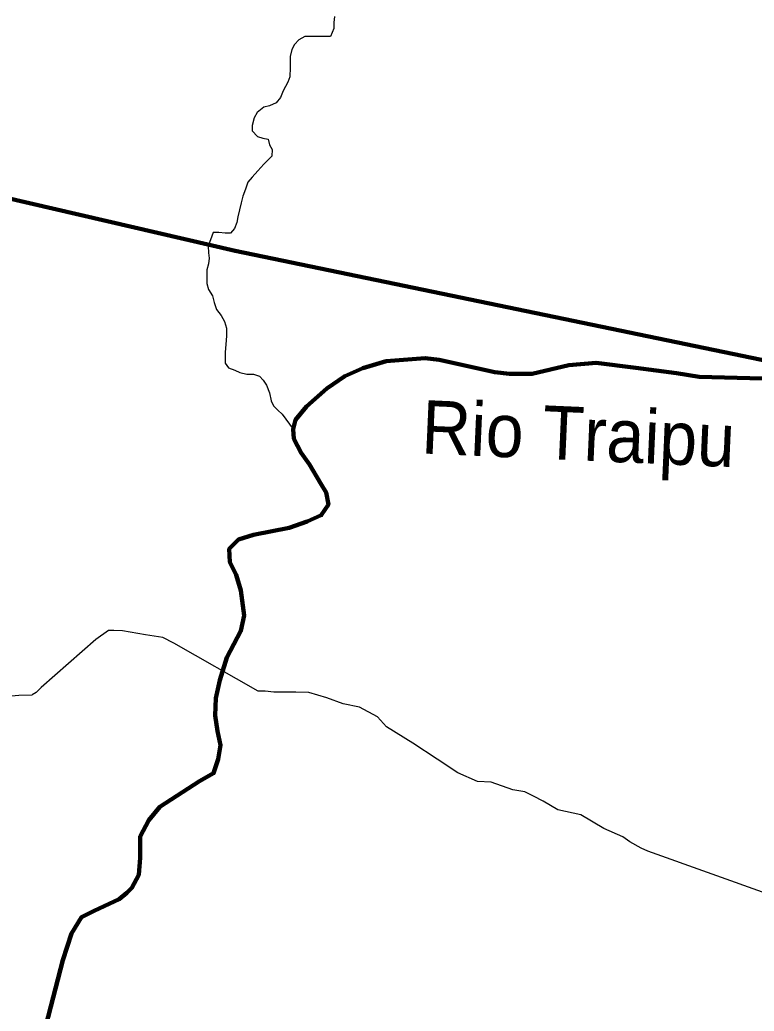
# Model space of a CAD drawing. Extents: x 553962 to 842807, y 8883888 to 9032388.
# Drawn here: x 722813 to 729677, y 8928998 to 8938264 of the extents above; entities that cross this region are included whole.
import ezdxf
from ezdxf.enums import TextEntityAlignment as Align

# ---------------------------------------------------------------- set-up
doc = ezdxf.new("R2010")
doc.units = 0
doc.header["$LTSCALE"] = 200
for name, color, linetype, lineweight in [('12', 7, 'Continuous', 25), ('24', 7, 'Continuous', 25), ('9', 7, 'Continuous', 90)]:
    doc.layers.add(name, color=color, linetype=linetype, lineweight=lineweight)
doc.layers.add('49', color=7, linetype='Continuous')

msp = doc.modelspace()

# ---------------------------------------------------------------- linework, layer by layer
at = {"layer": '12'}
for points in [[(729842.6, 8930080), (728682.6, 8930494.7), (728621.5, 8930520.3), (728514.8, 8930581.6), (728448.7, 8930627.6), (728270.7, 8930704.3), (728057.2, 8930832.1), (727843.4, 8930878.3), (727706.2, 8930960.1), (727614.7, 8931006.1), (727533.3, 8931047), (727421.3, 8931067.6), (727217.8, 8931139.3), (727090.4, 8931144.6), (726907.3, 8931226.4), (726714.2, 8931354.1), (726485.5, 8931502.3), (726241.6, 8931655.6), (726155.3, 8931747.4), (725987.5, 8931839.4), (725834.8, 8931870.3), (725682.2, 8931926.6), (725514.3, 8931977.8), (725392, 8931978.1), (725274.8, 8931978.3), (725188.2, 8931978.4), (725106.8, 8931988.8), (725040.5, 8931988.9), (724252.6, 8932438.6), (724150.9, 8932489.8), (723987.9, 8932515.5), (723774.1, 8932551.6), (723692.6, 8932556.8), (723641.7, 8932556.9), (723524.2, 8932470.5)], [(723524.2, 8932470.5), (723013.1, 8932023.2), (722964.6, 8931975.3), (722928.4, 8931953)], [(719465.7, 8931582), (719776.2, 8931594.6), (719960.1, 8931621.3), (720108, 8931671.9), (720470.6, 8931895.4), (720598.2, 8931961.4), (720664.5, 8932002), (720792.1, 8932052.7), (720970.4, 8932052.4), (721113, 8932057.2), (721235.3, 8932046.8), (721439, 8932046.4), (721540.8, 8932020.8), (721759.6, 8931949.1), (721968.3, 8931907.9), (722065, 8931877.2), (722233.1, 8931866.7), (722309.4, 8931841.1), (722477.5, 8931835.7), (722554, 8931861), (722651, 8931906.7), (722697, 8931942.3), (722804, 8931952.2), (722928.4, 8931953)]]:
    msp.add_lwpolyline(points, dxfattribs=at)
at = {"layer": '24'}
for points in [[(725753.9, 8938294.8), (725748.4, 8938238.8), (725748, 8938182.8), (725717, 8938106.6), (725544.1, 8938107.6), (725478, 8938108), (725421.8, 8938077.8), (725380.8, 8938032.2), (725355.1, 8937986.6), (725339.3, 8937920.5), (725339, 8937869.5), (725338.6, 8937818.6), (725338, 8937732.1), (725317.3, 8937681.2), (725276.1, 8937600), (725250.2, 8937539.1), (725207.8, 8937489.4), (725146.5, 8937460.6), (725092.5, 8937446.2), (725030.6, 8937397.8), (725004.8, 8937347.1), (724984, 8937275.9), (724983.6, 8937225), (725034.1, 8937173.8), (725084.8, 8937158.2), (725135.6, 8937147.7), (725145.5, 8937096.7), (725170.6, 8937050.7), (725170.1, 8936989.6), (725134.3, 8936954.2), (725093.3, 8936913.7), (725037, 8936852.9), (724985.7, 8936792.1), (724944.7, 8936746.5), (724923.9, 8936680.5), (724898, 8936614.4), (724882.3, 8936553.4), (724866.6, 8936487.3), (724850.9, 8936421.2), (724840.4, 8936370.3), (724819.6, 8936314.4), (724783.7, 8936268.8), (724732.8, 8936269.1), (724671.9, 8936274.6), (724621, 8936274.9)], [(724621, 8936274.9), (724573, 8936146.7), (724577.7, 8936085.6), (724582.4, 8936034.6), (724577, 8935983.7), (724561.3, 8935927.8), (724561, 8935876.9), (724560.4, 8935800.5), (724575.3, 8935744.4), (724615.6, 8935683), (724630.4, 8935621.8), (724650.3, 8935555.5), (724695.7, 8935499.2), (724725.8, 8935443), (724745.7, 8935381.8), (724745.2, 8935310.5), (724739.6, 8935229), (724734, 8935157.8), (724733.7, 8935106.9), (724733.3, 8935055.9), (724763.5, 8935009.9), (724824.4, 8934989.2), (724870, 8934968.5), (724936, 8934952.8), (724997.1, 8934952.5), (725052.8, 8934931.8), (725088.2, 8934895.9), (725118.4, 8934849.9), (725148.4, 8934778.4), (725163.2, 8934701.9), (725183.2, 8934656), (725223.6, 8934615), (725264, 8934579.1), (725368.5, 8934436.4)]]:
    msp.add_lwpolyline(points, dxfattribs=at)
at = {"layer": '24', "lineweight": 53}
for points in [[(726733.4, 8935086.7), (726602, 8935101.3), (726237.1, 8935072), (726018.1, 8935006.3), (725850.2, 8934933.2), (725682.3, 8934816.3), (725492.6, 8934648.3), (725390.4, 8934524.1), (725368.5, 8934436.4), (725375.8, 8934348.7), (725441.5, 8934217.2), (725521.8, 8934107.6), (725624, 8933932.2), (725675.1, 8933844.6), (725697, 8933734.9), (725631.3, 8933632.7), (725499.9, 8933574.2), (725332, 8933515.8), (724996.3, 8933450), (724857.6, 8933406.2), (724770, 8933318.5), (724777.3, 8933194.3), (724835.7, 8933077.4), (724879.5, 8932931.2), (724908.7, 8932697.4), (724879.5, 8932551.3), (724748.1, 8932302.9), (724682.4, 8932091), (724645.9, 8931922.9), (724638.6, 8931762.2), (724660.5, 8931616.1), (724689.7, 8931484.6), (724667.8, 8931353), (724624, 8931221.5), (724492.7, 8931148.4), (724120.4, 8930907.3), (724018.2, 8930783.1)], [(729755, 8934911.3), (729163.8, 8934925.9), (728952.2, 8934962.4), (728571.5, 8935009.7), (728200.4, 8935057.4), (727944.9, 8935035.5), (727601.9, 8934955.1), (727390.2, 8934955.1), (727251.6, 8934969.8), (726733.4, 8935086.7)], [(724018.2, 8930783.1), (723938, 8930629.7), (723938, 8930432.4), (723924.2, 8930271.2), (723861.2, 8930151.4), (723813.9, 8930103.6), (723741.7, 8930044.3), (723507.3, 8929935.6), (723390.6, 8929877.1), (723295.7, 8929723.7), (723215.4, 8929475.3), (723055.5, 8928859.6)]]:
    msp.add_lwpolyline(points, dxfattribs=at)
at = {"layer": '9'}
for points in [[(696242, 8937672.8), (702061.8, 8937200.5), (702208.9, 8933124.7), (710319.1, 8936704.6), (716154, 8938115.2), (724825.2, 8936103.1), (730092.7, 8935013.9)], [(726733.4, 8935086.7), (726602, 8935101.3), (726237.1, 8935072), (726018.1, 8935006.3), (725850.2, 8934933.2), (725682.3, 8934816.3), (725492.6, 8934648.3), (725390.4, 8934524.1), (725368.5, 8934436.4), (725375.8, 8934348.7), (725441.5, 8934217.2), (725521.8, 8934107.6), (725624, 8933932.2), (725675.1, 8933844.6), (725697, 8933734.9), (725631.3, 8933632.7), (725499.9, 8933574.2), (725332, 8933515.8), (724996.3, 8933450), (724857.6, 8933406.2), (724770, 8933318.5), (724777.3, 8933194.3), (724835.7, 8933077.4), (724879.5, 8932931.2), (724908.7, 8932697.4), (724879.5, 8932551.3), (724748.1, 8932302.9), (724682.4, 8932091), (724645.9, 8931922.9), (724638.6, 8931762.2), (724660.5, 8931616.1), (724689.7, 8931484.6), (724667.8, 8931353), (724624, 8931221.5), (724492.7, 8931148.4), (724120.4, 8930907.3), (724018.2, 8930783.1)], [(729755, 8934911.3), (729163.8, 8934925.9), (728952.2, 8934962.4), (728571.5, 8935009.7), (728200.4, 8935057.4), (727944.9, 8935035.5), (727601.9, 8934955.1), (727390.2, 8934955.1), (727251.6, 8934969.8), (726733.4, 8935086.7)], [(724018.2, 8930783.1), (723938, 8930629.7), (723938, 8930432.4), (723924.2, 8930271.2), (723861.2, 8930151.4), (723813.9, 8930103.6), (723741.7, 8930044.3), (723507.3, 8929935.6), (723390.6, 8929877.1), (723295.7, 8929723.7), (723215.4, 8929475.3), (723055.5, 8928859.6)]]:
    msp.add_lwpolyline(points, dxfattribs=at)

# ---------------------------------------------------------------- texts
at = {"layer": '49', "width": 0.95}
msp.add_text('Rio Traipu', height=500, rotation=357.482, dxfattribs=at).set_placement((728023.7, 8934146.6), align=Align.CENTER)

doc.saveas('drawing.dxf')
